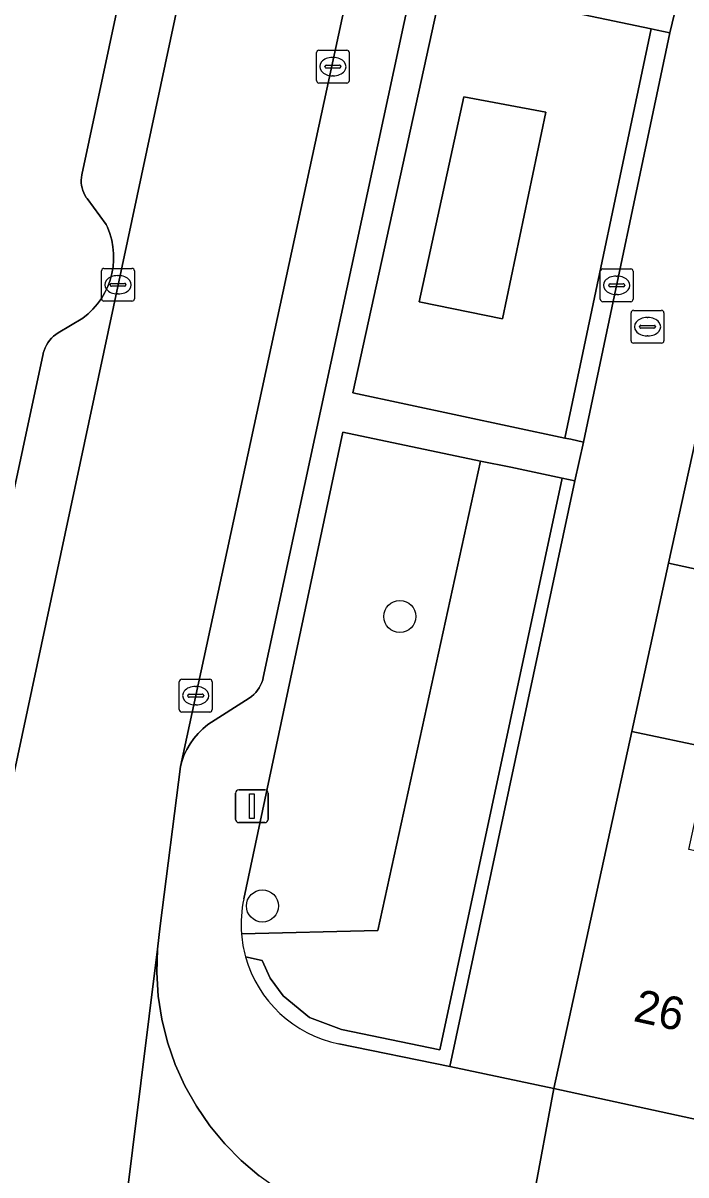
# Model space of a CAD drawing. Extents: x 160856 to 161310, y 384024 to 384878.
# Drawn here: x 161133.27 to 161153.45, y 384750.28 to 384785.38 of the extents above; entities that cross this region are included whole.
import ezdxf

# ---------------------------------------------------------------- set-up
doc = ezdxf.new("R2010")
doc.units = 0
for name, color, linetype in [('IMGEO_Boom', 7, 'Continuous'), ('IMGEO_Brandkraan', 7, 'Continuous'), ('IMGEO_Groenvoorziening', 7, 'Continuous'), ('IMGEO_Haag', 7, 'Continuous'), ('IMGEO_Kolk', 7, 'Continuous'), ('IMGEO_Lichtmast', 7, 'Continuous'), ('IMGEO_Pand', 7, 'Continuous'), ('IMGEO_Pand_nummerreeks', 7, 'Continuous'), ('IMGEO_Parkeervlak_open', 7, 'Continuous'), ('IMGEO_Rijbaan_lokaal_open', 7, 'Continuous'), ('IMGEO_Voetpad_open', 7, 'Continuous')]:
    doc.layers.add(name, color=color, linetype=linetype)

msp = doc.modelspace()

# ---------------------------------------------------------------- linework, layer by layer
at = {"layer": 'IMGEO_Boom'}
for centre in [(161144.74, 384767.295), (161140.557, 384758.474)]:
    msp.add_circle(centre, 0.489, dxfattribs=at)
at = {"layer": 'IMGEO_Brandkraan'}
for p, q in [((161151.855, 384776.624), (161152.707, 384776.624)), ((161151.78, 384775.698), (161151.78, 384776.55)), ((161152.268, 384776.404), (161152.293, 384776.404)), ((161152.781, 384776.55), (161152.781, 384775.698)), ((161152.039, 384776.118), (161152.039, 384776.13)), ((161152.477, 384776.081), (161152.079, 384776.081)), ((161152.082, 384776.167), (161152.48, 384776.167)), ((161152.523, 384776.13), (161152.523, 384776.118)), ((161152.707, 384775.624), (161151.855, 384775.624)), ((161152.291, 384775.844), (161152.266, 384775.844))]:
    msp.add_line(p, q, dxfattribs=at)
for points in [[(161151.855, 384776.624), (161152.707, 384776.624)], [(161151.78, 384775.698), (161151.78, 384776.55)], [(161152.781, 384776.55), (161152.781, 384775.698)], [(161152.707, 384775.624), (161151.855, 384775.624)]]:
    msp.add_lwpolyline(points, dxfattribs=at)
for centre, radius, start, end in [((161151.857, 384776.548), 0.0765, 91.552, 178.448), ((161151.857, 384776.548), 0.0765, 91.552, 178.448), ((161152.705, 384776.548), 0.0765, 1.552, 88.448), ((161152.705, 384776.548), 0.0765, 1.552, 88.448), ((161152.079, 384776.127), 0.0403, 85.8775, 175.7526), ((161152.076, 384776.117), 0.0366, 178.938, 274.7102), ((161152.48, 384776.124), 0.043, 264.8664, 352.4533), ((161152.484, 384776.129), 0.0386, 1.7309, 96.639), ((161151.857, 384775.7), 0.0765, 181.552, 268.448), ((161151.857, 384775.7), 0.0765, 181.552, 268.448), ((161152.705, 384775.7), 0.0765, 271.552, 358.448), ((161152.705, 384775.7), 0.0765, 271.552, 358.448)]:
    msp.add_arc(centre, radius, start, end, dxfattribs=at)
for centre, major_axis, ratio, start_param, end_param in [((161152.267, 384776.124), (-0.387, 0.002), 0.722429, 4.712389, 7.853982), ((161152.292, 384776.124), (-0.39, 0.002), 0.717154, 1.570796, 4.712389)]:
    msp.add_ellipse(centre, major_axis=major_axis, ratio=ratio, start_param=start_param, end_param=end_param, dxfattribs=at)
at = {"layer": 'IMGEO_Groenvoorziening'}
for points in [[(161146.032, 384786.541), (161143.313, 384774.11), (161149.765, 384772.732), (161152.395, 384785.201)], [(161149.945, 384772.694), (161150.336, 384772.611), (161152.964, 384785.082), (161152.572, 384785.164), (161152.395, 384785.201), (161149.765, 384772.732)], [(161145.328, 384776.888), (161146.689, 384783.13), (161149.186, 384782.667), (161147.869, 384776.363)], [(161147.869, 384776.363), (161149.186, 384782.667), (161146.689, 384783.13), (161145.328, 384776.888)]]:
    msp.add_lwpolyline(points, close=True, dxfattribs=at)
for points in [[(161139.921, 384757.624), (161144.069, 384757.724), (161147.2, 384772.032), (161143.005, 384772.91), (161139.99, 384758.692)], [(161140.045, 384756.923), (161140.55, 384756.817), (161140.791, 384756.279), (161141.187, 384755.733), (161141.993, 384755.081), (161142.969, 384754.71), (161145.959, 384754.094), (161149.681, 384771.513), (161148.115, 384771.841), (161147.2, 384772.032), (161144.069, 384757.724), (161139.921, 384757.624)], [(161142.879, 384754.275), (161146.258, 384753.579), (161150.072, 384771.431), (161149.681, 384771.513), (161145.959, 384754.094), (161142.969, 384754.71), (161141.993, 384755.081), (161141.187, 384755.733), (161140.791, 384756.279), (161140.55, 384756.817), (161140.045, 384756.923)]]:
    msp.add_lwpolyline(points, dxfattribs=at)
for centre, radius, start, end in [((161143.643, 384757.92), 3.733, 168.0627, 184.5442), ((161143.606, 384757.914), 3.697, 184.5061, 195.5565), ((161143.633, 384757.922), 3.724, 195.5613, 258.3253)]:
    msp.add_arc(centre, radius, start, end, dxfattribs=at)
at = {"layer": 'IMGEO_Haag'}
msp.add_lwpolyline([(161149.945, 384772.694), (161150.336, 384772.611), (161152.964, 384785.082), (161152.572, 384785.164), (161152.395, 384785.201), (161149.765, 384772.732)], close=True, dxfattribs=at)
msp.add_lwpolyline([(161142.879, 384754.275), (161146.258, 384753.579), (161150.072, 384771.431), (161149.681, 384771.513), (161145.959, 384754.094), (161142.969, 384754.71), (161141.993, 384755.081), (161141.187, 384755.733), (161140.791, 384756.279), (161140.55, 384756.817), (161140.045, 384756.923)], dxfattribs=at)
msp.add_arc((161143.633, 384757.922), 3.724, 195.5613, 258.3253, dxfattribs=at)
at = {"layer": 'IMGEO_Kolk'}
for p, q in [((161142.202, 384783.624), (161142.202, 384784.476)), ((161142.277, 384784.55), (161143.129, 384784.55)), ((161143.203, 384784.476), (161143.203, 384783.624)), ((161142.461, 384784.044), (161142.461, 384784.056)), ((161142.899, 384784.007), (161142.501, 384784.007)), ((161142.504, 384784.093), (161142.902, 384784.093)), ((161142.69, 384784.33), (161142.715, 384784.33)), ((161142.945, 384784.056), (161142.945, 384784.044)), ((161142.713, 384783.77), (161142.688, 384783.77)), ((161143.129, 384783.55), (161142.277, 384783.55)), ((161135.659, 384776.977), (161135.659, 384777.829)), ((161135.734, 384777.903), (161136.586, 384777.903)), ((161136.147, 384777.683), (161136.172, 384777.683)), ((161136.66, 384777.829), (161136.66, 384776.977)), ((161150.843, 384776.961), (161150.843, 384777.813)), ((161150.918, 384777.887), (161151.77, 384777.887)), ((161151.331, 384777.667), (161151.356, 384777.667)), ((161151.844, 384777.813), (161151.844, 384776.961)), ((161135.918, 384777.397), (161135.918, 384777.409)), ((161136.356, 384777.36), (161135.958, 384777.36)), ((161135.961, 384777.446), (161136.359, 384777.446)), ((161136.402, 384777.409), (161136.402, 384777.397)), ((161151.102, 384777.381), (161151.102, 384777.393)), ((161151.54, 384777.344), (161151.142, 384777.344)), ((161151.145, 384777.43), (161151.543, 384777.43)), ((161151.586, 384777.393), (161151.586, 384777.381)), ((161136.17, 384777.123), (161136.145, 384777.123)), ((161151.354, 384777.107), (161151.329, 384777.107)), ((161136.586, 384776.903), (161135.734, 384776.903)), ((161151.77, 384776.887), (161150.918, 384776.887)), ((161138.102, 384765.383), (161138.954, 384765.383)), ((161138.027, 384764.457), (161138.027, 384765.309)), ((161138.515, 384765.163), (161138.54, 384765.163)), ((161139.028, 384765.309), (161139.028, 384764.457)), ((161138.286, 384764.877), (161138.286, 384764.889)), ((161138.724, 384764.84), (161138.326, 384764.84)), ((161138.329, 384764.926), (161138.727, 384764.926)), ((161138.77, 384764.889), (161138.77, 384764.877)), ((161138.954, 384764.383), (161138.102, 384764.383)), ((161138.538, 384764.603), (161138.513, 384764.603))]:
    msp.add_line(p, q, dxfattribs=at)
for points in [[(161142.202, 384783.624), (161142.202, 384784.476)], [(161142.277, 384784.55), (161143.129, 384784.55)], [(161143.203, 384784.476), (161143.203, 384783.624)], [(161143.129, 384783.55), (161142.277, 384783.55)], [(161135.659, 384776.977), (161135.659, 384777.829)], [(161135.734, 384777.903), (161136.586, 384777.903)], [(161136.66, 384777.829), (161136.66, 384776.977)], [(161150.843, 384776.961), (161150.843, 384777.813)], [(161150.918, 384777.887), (161151.77, 384777.887)], [(161151.844, 384777.813), (161151.844, 384776.961)], [(161136.586, 384776.903), (161135.734, 384776.903)], [(161151.77, 384776.887), (161150.918, 384776.887)], [(161138.102, 384765.383), (161138.954, 384765.383)], [(161138.027, 384764.457), (161138.027, 384765.309)], [(161139.028, 384765.309), (161139.028, 384764.457)], [(161138.954, 384764.383), (161138.102, 384764.383)]]:
    msp.add_lwpolyline(points, dxfattribs=at)
for centre, radius, start, end in [((161142.279, 384784.474), 0.0765, 91.552, 178.448), ((161142.279, 384784.474), 0.0765, 91.552, 178.448), ((161143.127, 384784.474), 0.0765, 1.552, 88.448), ((161143.127, 384784.474), 0.0765, 1.552, 88.448), ((161142.501, 384784.053), 0.0403, 85.8775, 175.7526), ((161142.498, 384784.043), 0.0366, 178.938, 274.7102), ((161142.902, 384784.05), 0.043, 264.8664, 352.4533), ((161142.906, 384784.055), 0.0386, 1.7309, 96.639), ((161142.279, 384783.626), 0.0765, 181.552, 268.448), ((161142.279, 384783.626), 0.0765, 181.552, 268.448), ((161143.127, 384783.626), 0.0765, 271.552, 358.448), ((161143.127, 384783.626), 0.0765, 271.552, 358.448), ((161135.736, 384777.827), 0.0765, 91.552, 178.448), ((161135.736, 384777.827), 0.0765, 91.552, 178.448), ((161136.584, 384777.827), 0.0765, 1.552, 88.448), ((161136.584, 384777.827), 0.0765, 1.552, 88.448), ((161150.92, 384777.811), 0.0765, 91.552, 178.448), ((161150.92, 384777.811), 0.0765, 91.552, 178.448), ((161151.768, 384777.811), 0.0765, 1.552, 88.448), ((161151.768, 384777.811), 0.0765, 1.552, 88.448), ((161135.958, 384777.406), 0.0403, 85.8775, 175.7526), ((161135.955, 384777.396), 0.0366, 178.938, 274.7102), ((161136.359, 384777.403), 0.043, 264.8664, 352.4533), ((161136.363, 384777.408), 0.0386, 1.7309, 96.639), ((161151.142, 384777.39), 0.0403, 85.8775, 175.7526), ((161151.139, 384777.38), 0.0366, 178.938, 274.7102), ((161151.543, 384777.387), 0.043, 264.8664, 352.4533), ((161151.547, 384777.392), 0.0386, 1.7309, 96.639), ((161135.736, 384776.979), 0.0765, 181.552, 268.448), ((161135.736, 384776.979), 0.0765, 181.552, 268.448), ((161136.584, 384776.979), 0.0765, 271.552, 358.448), ((161136.584, 384776.979), 0.0765, 271.552, 358.448), ((161150.92, 384776.963), 0.0765, 181.552, 268.448), ((161150.92, 384776.963), 0.0765, 181.552, 268.448), ((161151.768, 384776.963), 0.0765, 271.552, 358.448), ((161151.768, 384776.963), 0.0765, 271.552, 358.448), ((161138.104, 384765.307), 0.0765, 91.552, 178.448), ((161138.104, 384765.307), 0.0765, 91.552, 178.448), ((161138.952, 384765.307), 0.0765, 1.552, 88.448), ((161138.952, 384765.307), 0.0765, 1.552, 88.448), ((161138.326, 384764.886), 0.0403, 85.8775, 175.7526), ((161138.323, 384764.876), 0.0366, 178.938, 274.7102), ((161138.727, 384764.883), 0.043, 264.8664, 352.4533), ((161138.731, 384764.888), 0.0386, 1.7309, 96.639), ((161138.104, 384764.459), 0.0765, 181.552, 268.448), ((161138.104, 384764.459), 0.0765, 181.552, 268.448), ((161138.952, 384764.459), 0.0765, 271.552, 358.448), ((161138.952, 384764.459), 0.0765, 271.552, 358.448)]:
    msp.add_arc(centre, radius, start, end, dxfattribs=at)
for centre, major_axis, ratio, start_param, end_param in [((161142.689, 384784.05), (-0.387, 0.002), 0.722429, 4.712389, 7.853982), ((161142.714, 384784.05), (-0.39, 0.002), 0.717154, 1.570796, 4.712389), ((161136.146, 384777.403), (-0.387, 0.002), 0.722429, 4.712389, 7.853982), ((161136.171, 384777.403), (-0.39, 0.002), 0.717154, 1.570796, 4.712389), ((161151.33, 384777.387), (-0.387, 0.002), 0.722429, 4.712389, 7.853982), ((161151.355, 384777.387), (-0.39, 0.002), 0.717154, 1.570796, 4.712389), ((161138.514, 384764.883), (-0.387, 0.002), 0.722429, 4.712389, 7.853982), ((161138.539, 384764.883), (-0.39, 0.002), 0.717154, 1.570796, 4.712389)]:
    msp.add_ellipse(centre, major_axis=major_axis, ratio=ratio, start_param=start_param, end_param=end_param, dxfattribs=at)
at = {"layer": 'IMGEO_Lichtmast'}
for p, q in [((161139.74, 384761.114), (161139.74, 384761.914)), ((161139.74, 384761.914), (161139.74, 384761.114)), ((161139.84, 384762.014), (161140.63, 384762.014)), ((161140.63, 384762.014), (161139.84, 384762.014)), ((161140.73, 384761.914), (161140.73, 384761.114)), ((161140.73, 384761.114), (161140.73, 384761.914)), ((161140.63, 384761.014), (161139.84, 384761.014)), ((161139.84, 384761.014), (161140.63, 384761.014))]:
    msp.add_line(p, q, dxfattribs=at)
msp.add_lwpolyline([(161140.16, 384761.889), (161140.31, 384761.889), (161140.31, 384761.139), (161140.16, 384761.139), (161140.16, 384761.889)], dxfattribs=at)
for centre, start, end in [((161139.84, 384761.914), 90, 180), ((161139.84, 384761.914), 90, 180), ((161140.63, 384761.914), 0, 90), ((161140.63, 384761.914), 360, 90), ((161139.84, 384761.114), 180, 270), ((161139.84, 384761.114), 180, 270), ((161140.63, 384761.114), 270, 0), ((161140.63, 384761.114), 270, 0)]:
    msp.add_arc(centre, 0.1, start, end, dxfattribs=at)
at = {"layer": 'IMGEO_Pand'}
for points in [[(161167.943, 384771.02), (161166.255, 384771.388), (161154.042, 384774.051), (161152.923, 384768.921), (161162.294, 384766.878), (161162.936, 384769.819), (161164.69, 384769.437), (161164.437, 384768.276), (161167.213, 384767.671)], [(161164.457, 384766.406), (161162.294, 384766.878), (161152.923, 384768.921), (161151.803, 384763.789), (161154.204, 384763.282), (161157.335, 384762.622), (161159.617, 384762.14), (161163.355, 384761.362)], [(161154.204, 384763.282), (161151.803, 384763.789), (161149.43, 384752.917), (161153.86, 384751.95), (161154.964, 384751.709), (161156.668, 384759.523), (161153.54, 384760.196)]]:
    msp.add_lwpolyline(points, close=True, dxfattribs=at)
at = {"layer": 'IMGEO_Parkeervlak_open'}
for points in [[(161132.813, 384761.681), (161144.864, 384818.229)], [(161147.796, 384807.819), (161138.061, 384762.728), (161138.101, 384762.876), (161138.169, 384763.064), (161138.254, 384763.245), (161138.354, 384763.418), (161138.469, 384763.581), (161138.599, 384763.734), (161138.741, 384763.874), (161138.896, 384764.001), (161140.152, 384764.811), (161140.224, 384764.862), (161140.291, 384764.92), (161140.353, 384764.984), (161140.409, 384765.052), (161140.458, 384765.126), (161140.501, 384765.203), (161140.537, 384765.284), (161140.565, 384765.368), (161140.581, 384765.432), (161148.99, 384804.556)], [(161138.197, 384795.457), (161135.063, 384780.749), (161135.05, 384780.67), (161135.043, 384780.591), (161135.044, 384780.511), (161135.052, 384780.432), (161135.067, 384780.354), (161135.089, 384780.277), (161135.118, 384780.203), (161135.153, 384780.132), (161135.194, 384780.064), (161135.219, 384780.029), (161135.804, 384779.238), (161135.84, 384779.158), (161135.913, 384778.965), (161135.969, 384778.767), (161136.006, 384778.564), (161136.025, 384778.358), (161136.026, 384778.152), (161136.009, 384777.946), (161135.973, 384777.743), (161135.919, 384777.543), (161135.847, 384777.35), (161135.759, 384777.163), (161135.654, 384776.986), (161135.534, 384776.818), (161135.399, 384776.661), (161135.25, 384776.518), (161135.09, 384776.388), (161134.337, 384775.937), (161134.264, 384775.889), (161134.196, 384775.834), (161134.133, 384775.774), (161134.075, 384775.708), (161134.024, 384775.637), (161133.979, 384775.562), (161133.941, 384775.484), (161133.91, 384775.402), (161133.887, 384775.318), (161133.883, 384775.302), (161130.744, 384760.685)]]:
    msp.add_lwpolyline(points, dxfattribs=at)
at = {"layer": 'IMGEO_Rijbaan_lokaal_open'}
for points in [[(161144.864, 384818.229), (161132.813, 384761.681), (161132.507, 384759.586), (161131.86, 384754.533), (161131.333, 384750), (161129.676, 384735.749), (161128.787, 384725.541), (161128.722, 384724.796), (161128.062, 384717.217)], [(161132.216, 384706.852), (161134.909, 384737.229), (161134.947, 384737.659), (161135.071, 384738.699), (161137.359, 384757.16), (161137.441, 384757.872), (161138.061, 384762.728), (161147.796, 384807.819)], [(161146.315, 384748.311), (161146.075, 384748.362), (161143.854, 384748.73), (161143.416, 384748.826), (161142.728, 384749.031), (161142.062, 384749.296), (161141.422, 384749.62), (161140.813, 384750), (161140.462, 384750.255), (161139.915, 384750.718), (161139.411, 384751.227), (161138.954, 384751.779), (161138.549, 384752.37), (161138.198, 384752.995), (161137.904, 384753.648), (161137.67, 384754.326), (161137.498, 384755.021), (161137.388, 384755.729), (161137.341, 384756.444), (161137.359, 384757.16), (161135.071, 384738.699)]]:
    msp.add_lwpolyline(points, dxfattribs=at)
at = {"layer": 'IMGEO_Voetpad_open'}
for points in [[(161139.99, 384758.692), (161143.005, 384772.91), (161147.2, 384772.032), (161148.115, 384771.841), (161149.681, 384771.513), (161150.072, 384771.431), (161150.336, 384772.611), (161149.945, 384772.694), (161149.765, 384772.732), (161143.313, 384774.11), (161146.032, 384786.541), (161152.395, 384785.201), (161152.572, 384785.164), (161152.964, 384785.082), (161153.252, 384786.312), (161152.86, 384786.395), (161152.73, 384786.422), (161146.23, 384787.791), (161150.501, 384807.501)], [(161148.99, 384804.556), (161140.581, 384765.432), (161140.565, 384765.368), (161140.537, 384765.284), (161140.501, 384765.203), (161140.458, 384765.126), (161140.409, 384765.052), (161140.353, 384764.984), (161140.291, 384764.92), (161140.224, 384764.862), (161140.152, 384764.811), (161138.896, 384764.001), (161138.741, 384763.874), (161138.599, 384763.734), (161138.469, 384763.581), (161138.354, 384763.418), (161138.254, 384763.245), (161138.169, 384763.064), (161138.101, 384762.876), (161138.061, 384762.728), (161137.441, 384757.872), (161137.359, 384757.16), (161137.341, 384756.444), (161137.388, 384755.729), (161137.498, 384755.021), (161137.67, 384754.326), (161137.904, 384753.648), (161138.198, 384752.995), (161138.549, 384752.37), (161138.954, 384751.779), (161139.411, 384751.227), (161139.915, 384750.718), (161140.462, 384750.255)], [(161130.744, 384760.685), (161133.883, 384775.302), (161133.887, 384775.318), (161133.91, 384775.402), (161133.941, 384775.484), (161133.979, 384775.562), (161134.024, 384775.637), (161134.075, 384775.708), (161134.133, 384775.774), (161134.196, 384775.834), (161134.264, 384775.889), (161134.337, 384775.937), (161135.09, 384776.388), (161135.25, 384776.518), (161135.399, 384776.661), (161135.534, 384776.818), (161135.654, 384776.986), (161135.759, 384777.163), (161135.847, 384777.35), (161135.919, 384777.543), (161135.973, 384777.743), (161136.009, 384777.946), (161136.026, 384778.152), (161136.025, 384778.358), (161136.006, 384778.564), (161135.969, 384778.767), (161135.913, 384778.965), (161135.84, 384779.158), (161135.804, 384779.238), (161135.219, 384780.029), (161135.194, 384780.064), (161135.153, 384780.132), (161135.118, 384780.203), (161135.089, 384780.277), (161135.067, 384780.354), (161135.052, 384780.432), (161135.044, 384780.511), (161135.043, 384780.591), (161135.05, 384780.67), (161135.063, 384780.749), (161138.197, 384795.457)], [(161182.508, 384755.488), (161177.774, 384753.546), (161173.04, 384751.605), (161169.125, 384750), (161166.925, 384749.098), (161165.374, 384749.437), (161162.793, 384750), (161160.248, 384750.556), (161154.964, 384751.709), (161153.86, 384751.95), (161149.43, 384752.917), (161148.811, 384749.577), (161148.889, 384749.607), (161148.969, 384749.629), (161149.051, 384749.645), (161149.134, 384749.653), (161149.218, 384749.654), (161149.301, 384749.647), (161153.319, 384748.994), (161162.18, 384747.553)], [(161148.811, 384749.577), (161149.43, 384752.917), (161146.258, 384753.579), (161142.879, 384754.275)]]:
    msp.add_lwpolyline(points, dxfattribs=at)
msp.add_lwpolyline([(161157.63, 384790.433), (161158.71, 384795.466), (161159.79, 384800.498), (161160.801, 384805.206), (161157.448, 384805.953), (161153.252, 384786.312), (161152.964, 384785.082), (161150.336, 384772.611), (161150.072, 384771.431), (161146.258, 384753.579), (161149.43, 384752.917), (161151.803, 384763.789), (161152.923, 384768.921), (161154.042, 384774.051), (161155.162, 384779.18), (161156.282, 384784.312), (161156.518, 384785.254)], close=True, dxfattribs=at)
for centre, radius, start, end in [((161143.643, 384757.92), 3.733, 168.0627, 184.5442), ((161143.606, 384757.914), 3.697, 184.5061, 195.5565), ((161143.633, 384757.922), 3.724, 195.5613, 258.3253)]:
    msp.add_arc(centre, radius, start, end, dxfattribs=at)

# ---------------------------------------------------------------- texts
at = {"layer": 'IMGEO_Pand_nummerreeks'}
msp.add_text('26', height=1, rotation=347.6875, dxfattribs=at).set_placement((161151.818, 384754.975))

doc.saveas('drawing.dxf')
